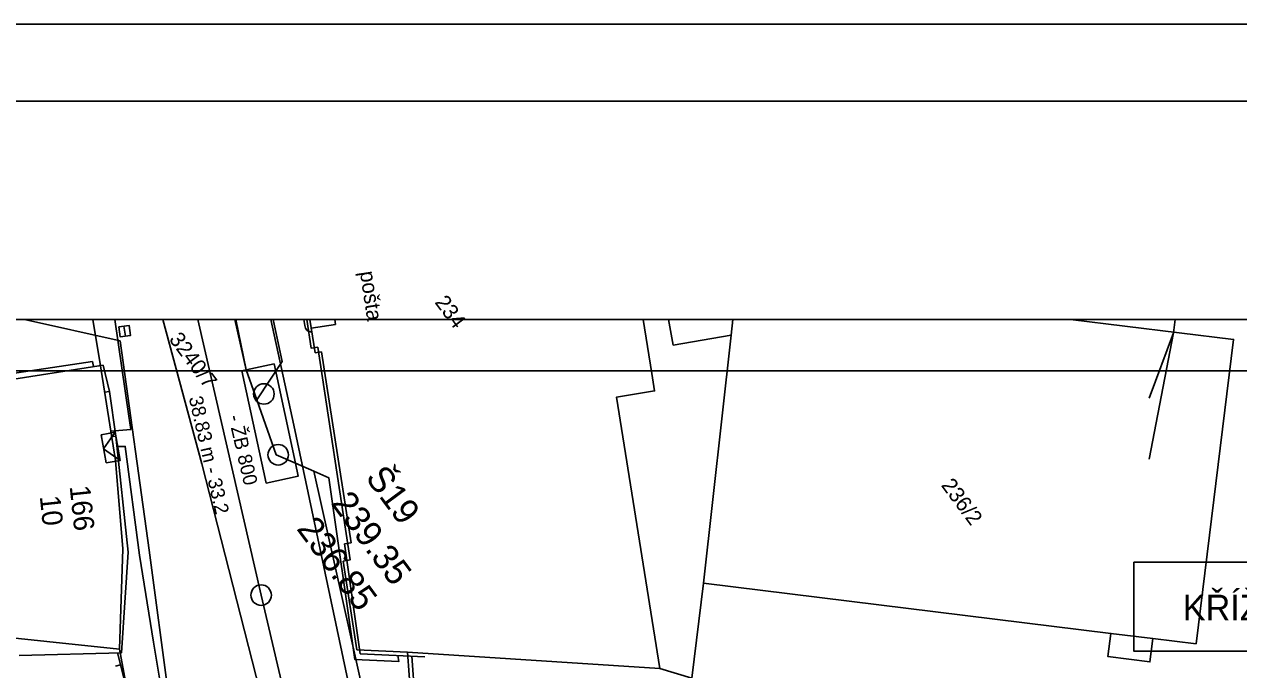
# Model space of a CAD drawing. Extents: x -601580 to 4, y -1204314 to 4.
# Drawn here: x -596051.4 to -595992.2, y -1202907 to -1202875.6 of the extents above; entities that cross this region are included whole.
import ezdxf

# ---------------------------------------------------------------- set-up
doc = ezdxf.new("R2010")
doc.units = 0
for name, color, linetype in [('00-EON NN', 7, 'Continuous'), ('00-KN-HRANICE PARCEL', 7, 'Continuous'), ('00-KN-PARC. CISLA', 7, 'Continuous'), ('00-KN-VNITRNI KRESBA', 7, 'Continuous'), ('00-POLOHOPIS', 7, 'Continuous'), ('00-RAZÍTKO', 7, 'Continuous'), ('00-SITE KOM. KABEL', 7, 'Continuous'), ('00-VAK-KANAL-POPIS', 7, 'Continuous'), ('00-VAK-KANAL-POTRUBI', 7, 'Continuous'), ('00-VAK-VODA-RAD IGIS', 7, 'Continuous'), ('11-REKONSTRUKCE KANALIZACE POPIS', 7, 'Continuous'), ('Vrstva 26', 7, 'Continuous'), ('Vrstva 27', 7, 'Continuous'), ('Vrstva 41', 7, 'Continuous'), ('Vrstva 6', 7, 'Continuous'), ('Vrstva 9', 7, 'Continuous')]:
    doc.layers.add(name, color=color, linetype=linetype)

# ---------------------------------------------------------------- blocks, each defined once
blk = doc.blocks.new('POS')
at = {"layer": 'Vrstva 41'}
blk.add_text('pošta', height=0.75, rotation=0, dxfattribs=at).set_placement((-1.238, -0.375))
blk = doc.blocks.new('VCHOD_2490')
at = {"layer": 'Vrstva 6'}
blk.add_line((0, 0.25), (0, 0), dxfattribs=at)
blk = doc.blocks.new('6.20D_500')
at = {"layer": 'Vrstva 27'}
blk.add_circle((0, 0), 0.5, dxfattribs=at)
blk = doc.blocks.new('6.20D_502')
at = {"layer": 'Vrstva 27'}
blk.add_circle((0, 0), 0.5, dxfattribs=at)
blk = doc.blocks.new('6.30_1136')
at = {"layer": 'Vrstva 27'}
blk.add_line((-0.25, 0), (0.25, 0), dxfattribs=at)
blk.add_lwpolyline([(-0.25, -0.25), (0.25, -0.25), (0.25, 0.25), (-0.25, 0.25)], close=True, dxfattribs=at)
blk = doc.blocks.new('VCHOD_4680')
at = {"layer": 'Vrstva 6'}
blk.add_line((0, 0.25), (0, 0), dxfattribs=at)
blk = doc.blocks.new('VCHOD_4682')
at = {"layer": 'Vrstva 6'}
blk.add_line((0, 0.25), (0, 0), dxfattribs=at)
blk = doc.blocks.new('NN630')
at = {"layer": 'Vrstva 9'}
for points in [[(-3, -700), (-703, 0)], [(-703, -700), (-703, 0), (697, 0), (697, -700)], [(-3, -700), (697, 0)], [(-703, -700), (697, -700)]]:
    blk.add_lwpolyline(points, dxfattribs=at)

msp = doc.modelspace()

# ---------------------------------------------------------------- linework, layer by layer
for points in [[(-595979.871, -1202875.568), (-596202.621, -1202875.568), (-596202.621, -1203190.718), (-595979.871, -1203190.718)], [(-595976.121, -1202879.318), (-596198.871, -1202879.318), (-596198.871, -1203186.968), (-595976.121, -1203186.968)], [(-595970.972, -1202892.468), (-595970.972, -1202889.968), (-596076.023, -1202889.968), (-596076.023, -1203038.468), (-595970.972, -1203038.468), (-595970.972, -1203035.968)], [(-595973.472, -1202892.468), (-596073.523, -1202892.468), (-596073.523, -1203035.968), (-595973.472, -1203035.968)]]:
    msp.add_lwpolyline(points)
at = {"layer": '00-EON NN'}
msp.add_lwpolyline([(-596030.018, -1202922.882), (-596030.03, -1202923.374), (-596031.613, -1202923.271), (-596032.638, -1202923.439), (-596038.181, -1202923.888), (-596039.256, -1202923.929), (-596039.543, -1202917.294), (-596039.786, -1202917.323), (-596040.091, -1202917.159), (-596039.834, -1202916.926), (-596039.572, -1202916.894), (-596040.053, -1202912.322), (-596040.264, -1202911.333), (-596040.878, -1202910.842), (-596042.484, -1202910.45), (-596044.3, -1202910.192), (-596044.682, -1202908.049), (-596045.073, -1202905.711), (-596045.751, -1202901.458), (-596046.447, -1202896.158), (-596046.818, -1202896.155)], dxfattribs=at)
at = {"layer": '00-KN-HRANICE PARCEL'}
for p, q in [((-596047.151, -1202895.411), (-596047.667, -1202892.132)), ((-596046.927, -1202896.838), (-596047.151, -1202895.411)), ((-596018.248, -1202902.825), (-596018.819, -1202907.458)), ((-596035.156, -1202906.085), (-596032.685, -1202906.193)), ((-596032.685, -1202906.193), (-596020.387, -1202906.99)), ((-596031.477, -1202922.669), (-596032.685, -1202906.193)), ((-596018.819, -1202907.458), (-596020.387, -1202906.99))]:
    msp.add_line(p, q, dxfattribs=at)
for points in [[(-596047.667, -1202892.132), (-596048.025, -1202889.968)], [(-596046.956, -1202889.968), (-596046.278, -1202894.675), (-596046.181, -1202895.326), (-596047.151, -1202895.411)], [(-596037.601, -1202889.968), (-596037.389, -1202891.365), (-596037.061, -1202891.321)], [(-596020.387, -1202906.99), (-596022.497, -1202893.761), (-596020.635, -1202893.451), (-596020.767, -1202892.602), (-596021.186, -1202889.968)], [(-596016.817, -1202889.968), (-596016.902, -1202890.729), (-596018.248, -1202902.825)], [(-596000.348, -1202889.968), (-595992.401, -1202890.937), (-595994.232, -1202905.784), (-595996.339, -1202905.529), (-595996.479, -1202906.667), (-595998.527, -1202906.407), (-595998.382, -1202905.277), (-596018.248, -1202902.825)], [(-596037.061, -1202891.321), (-596035.487, -1202901.697), (-596035.817, -1202901.755), (-596035.156, -1202906.085)], [(-596046.724, -1202906.053), (-596046.572, -1202901.158), (-596046.927, -1202896.838)], [(-596062.496, -1202904.385), (-596060.039, -1202904.641), (-596057.379, -1202904.92), (-596046.724, -1202906.053)], [(-596039.898, -1202926.205), (-596040.438, -1202912.359), (-596045.739, -1202911.424), (-596046.224, -1202908.758), (-596046.724, -1202906.053)]]:
    msp.add_lwpolyline(points, dxfattribs=at)
at = {"layer": '00-KN-VNITRNI KRESBA'}
for p, q in [((-596019.734, -1202891.225), (-596019.956, -1202889.968)), ((-596016.902, -1202890.729), (-596019.734, -1202891.225)), ((-595996.339, -1202905.529), (-595998.382, -1202905.277))]:
    msp.add_line(p, q, dxfattribs=at)
at = {"layer": '00-POLOHOPIS'}
for p, q in [((-596051.372, -1202889.968), (-596046.704, -1202891.007)), ((-596039.344, -1202889.968), (-596038.23, -1202895.123)), ((-596037.735, -1202889.968), (-596037.688, -1202890.267)), ((-596037.45, -1202889.968), (-596037.197, -1202891.585)), ((-596036.234, -1202889.968), (-596036.197, -1202890.206)), ((-596036.197, -1202890.206), (-596037.383, -1202890.392)), ((-596046.704, -1202891.007), (-596045.281, -1202901.223)), ((-596037.197, -1202891.585), (-596036.88, -1202891.537)), ((-596036.88, -1202891.537), (-596035.441, -1202900.859)), ((-596055.312, -1202893.112), (-596048.042, -1202892.011)), ((-596055.266, -1202893.408), (-596047.533, -1202892.187)), ((-596048.002, -1202892.261), (-596048.042, -1202892.011)), ((-596047.22, -1202893.479), (-596047.533, -1202892.187)), ((-596047.22, -1202893.479), (-596046.909, -1202895.654)), ((-596047.22, -1202893.479), (-596046.909, -1202895.654)), ((-596038.23, -1202895.123), (-596034.143, -1202914.386)), ((-596045.281, -1202901.223), (-596044.081, -1202910.243)), ((-596035.441, -1202900.859), (-596035.759, -1202900.908)), ((-596035.759, -1202900.908), (-596035, -1202906.268)), ((-596051.63, -1202906.351), (-596046.632, -1202906.22)), ((-596046.833, -1202906.226), (-596046.115, -1202909.054)), ((-596035, -1202906.268), (-596031.837, -1202906.419)), ((-596032.328, -1202908.398), (-596032.471, -1202906.389)), ((-596046.115, -1202909.054), (-596046.685, -1202906.807))]:
    msp.add_line(p, q, dxfattribs=at)
msp.add_lwpolyline([(-596046.909, -1202895.654), (-596046.315, -1202901.311), (-596046.632, -1202906.22)], dxfattribs=at)
msp.add_arc((-596037.382, -1202890.271), 0.305, 179.27597, 275.0662, dxfattribs=at)
at = {"layer": '00-RAZÍTKO'}
for points in [[(-596076.023, -1202889.968), (-595760.871, -1202889.968), (-595760.871, -1203038.468), (-596076.023, -1203038.468)], [(-596073.523, -1202892.468), (-595763.371, -1202892.468), (-595763.371, -1203035.968), (-596073.523, -1203035.968)]]:
    msp.add_lwpolyline(points, close=True, dxfattribs=at)
at = {"layer": '00-SITE KOM. KABEL'}
for points in [[(-596040.034, -1202893.888), (-596040.554, -1202892.42), (-596041.104, -1202889.968)], [(-596040.034, -1202893.888), (-596040.554, -1202892.42), (-596041.104, -1202889.968)], [(-596040.554, -1202892.42), (-596041.057, -1202889.968)], [(-596039.242, -1202889.968), (-596038.799, -1202892.023), (-596040.034, -1202893.888)], [(-595995.252, -1202889.968), (-595995.335, -1202890.624)], [(-595995.252, -1202889.968), (-595995.335, -1202890.624)], [(-595995.252, -1202889.968), (-595995.335, -1202890.624)], [(-595995.335, -1202890.624), (-595996.524, -1202896.774)], [(-595995.335, -1202890.624), (-595996.524, -1202896.774)], [(-595995.335, -1202890.624), (-595996.523, -1202893.802)], [(-596038.147, -1202896.972), (-596039.087, -1202896.561), (-596040.034, -1202893.888)], [(-596038.147, -1202896.972), (-596039.087, -1202896.561), (-596040.034, -1202893.888)], [(-596037.255, -1202897.368), (-596038.147, -1202896.972)], [(-596037.255, -1202897.368), (-596038.147, -1202896.972)], [(-596034.806, -1202908.352), (-596037.255, -1202897.368)], [(-596034.806, -1202908.352), (-596037.255, -1202897.368)], [(-596037.255, -1202897.368), (-596036.518, -1202897.693), (-596035.26, -1202906.547), (-596033.116, -1202906.65), (-596033.162, -1202906.354)]]:
    msp.add_lwpolyline(points, dxfattribs=at)
msp.add_lwpolyline([(-596039.197, -1202892.134), (-596040.554, -1202892.42), (-596040.769, -1202892.467), (-596039.578, -1202897.947), (-596038.012, -1202897.606), (-596038.147, -1202896.972)], close=True, dxfattribs=at)
at = {"layer": '00-VAK-KANAL-POTRUBI'}
for p, q in [((-596042.916, -1202889.968), (-596039.823, -1202903.41)), ((-596039.823, -1202903.41), (-596033.841, -1202928.891))]:
    msp.add_line(p, q, dxfattribs=at)
msp.add_circle((-596039.823, -1202903.41), 0.5, dxfattribs=at)
at = {"layer": '00-VAK-VODA-RAD IGIS'}
msp.add_lwpolyline([(-596044.622, -1202889.968), (-596042.71, -1202897.014), (-596039.128, -1202911.071), (-596037.815, -1202928.76), (-596038.392, -1202932.976)], dxfattribs=at)
at = {"layer": '11-REKONSTRUKCE KANALIZACE POPIS'}
msp.add_lwpolyline([(-595997.271, -1202901.802), (-595973.595, -1202901.802), (-595973.595, -1202906.137), (-595997.271, -1202906.137)], close=True, dxfattribs=at)

# ---------------------------------------------------------------- block references
at = {"layer": '00-POLOHOPIS'}
for name, p, xscale, yscale, rotation in [('POS', (-596034.454, -1202888.817), 1.0000004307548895, 1.0000004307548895, -81.30440717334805), ('6.30_1136', (-596046.48, -1202890.537), 0.9999988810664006, 0.9999988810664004, -82.06696152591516), ('VCHOD_4680', (-596047.22, -1202893.479), 1.0000012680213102, 1.0000012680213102, 98.15391434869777), ('VCHOD_4682', (-596046.909, -1202895.654), 1.0000012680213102, 1.0000012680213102, 98.15391434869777), ('VCHOD_2490', (-596046.685, -1202906.807), 0.9999995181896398, 0.9999995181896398, 104.24678993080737)]:
    msp.add_blockref(name, p, dxfattribs=dict(at, xscale=xscale, yscale=yscale, rotation=rotation))
at = {"layer": '00-POLOHOPIS', "rotation": 36.585318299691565}
for name, p in [('6.20D_502', (-596039.689, -1202893.598)), ('6.20D_500', (-596038.992, -1202896.565))]:
    msp.add_blockref(name, p, dxfattribs=at)
at = {"layer": 'Vrstva 26', "xscale": 0.0010000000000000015, "yscale": 0.001000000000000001, "rotation": -79.78780667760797}
msp.add_blockref('NN630', (-596046.819, -1202896.155), dxfattribs=at)

# ---------------------------------------------------------------- texts
at = {"layer": '00-KN-PARC. CISLA'}
for s, p in [('234', (-596031.386, -1202889.134)), ('3240/7', (-596044.347, -1202890.935)), ('236/2', (-596006.692, -1202898.058))]:
    msp.add_text(s, height=0.75, rotation=306.58532, dxfattribs=at).set_placement(p)
at = {"layer": '00-POLOHOPIS'}
for s, p in [('166', (-596049.165, -1202898.102)), ('10', (-596050.622, -1202898.595))]:
    msp.add_text(s, height=1, rotation=275.98953, dxfattribs=at).set_placement(p)
at = {"layer": '00-VAK-KANAL-POPIS'}
for s, height, rotation, p in [('38.83 m - 33.2', 0.68241, 282.95751, (-596043.358, -1202893.784)), ('- ŽB 800', 0.6824, 282.95751, (-596041.431, -1202894.696)), ('Š19', 1.25, 306.58532, (-596034.775, -1202897.69)), ('239.35', 1.25, 306.58532, (-596036.452, -1202898.935)), ('236.85', 1.25, 306.58532, (-596038.129, -1202900.179))]:
    msp.add_text(s, height=height, rotation=rotation, dxfattribs=at).set_placement(p)
at = {"layer": '11-REKONSTRUKCE KANALIZACE POPIS'}
msp.add_text('KŘÍŽENÍ VN. EL. KABEL', height=1.25, dxfattribs=at).set_placement((-595994.883, -1202904.641))

doc.saveas('drawing.dxf')
